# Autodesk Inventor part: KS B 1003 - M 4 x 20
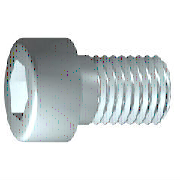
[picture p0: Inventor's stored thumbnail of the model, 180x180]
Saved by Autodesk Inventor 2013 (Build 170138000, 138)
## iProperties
IsCustomPart: 1
Company: 한국ATC센터
Created: 2009-02
Part Number: KS B 1003 - M 4 x 20
Material: 강철, 연강
Description: 6각머리 태핑 나사
Document SubType Name: Modeling
Standard: KS B 1003
Designer: KYOUNG IL JANG
Standards Organization: KS
Language: ko-KR
Size Designation: M 4 x 20
Categories: <MemberInstance><Categories><Category DisplayName="조임쇠" InternalName="e4da775c-781d-43d5-af7c-5136215cf5a6" Mnemonic="FSTN"><Category DisplayName="볼트" InternalN
Density: 7.86 g/cm^3
Mass: 2.43327 g
Surface Area: 3.56234 cm^2
Volume: 0.309576 cm^3
Vendor: CBT Solutions
Author: KYOUNG IL JANG
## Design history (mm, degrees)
sketch "스케치1"
  geometry: L1 (-1, 0)-(20, 0); L2 (20, 0)-(20, 2); L3 (20, 2)-(1.75, 2); L4 (1.75, 2)-(1.32, 2); L5 (1.32, 2)-(0, 2); L6 (0, 2)-(0, 3.5); L7 (0, 3.5)-(-4, 3.5); L8 (-4, 3.5)-(-4, 1.732); L9 (-4, 1.732)-(-2, 1.732); L10 (-2, 1.732)-(-1, 0); L11 (-8.8, 0)-(24.8, 0) reference; L12 (0, -0.7)-(0, 4.2) reference; L13 (1.75, 2)-(0, 2)
  constraints: 22 end point, 6 parallel, 2 collinear, 2 perpendicular, 1 horizontal, 1 point on line
  dimensions: "d1" = 18.25 distance from line of L3.end L2 (= GEL); "d2" = 0.42952 distance of L4.end L3.end (computed from GAL); "d3" = 4 distance between parallel lines of L8 L6 (= KOH); "d4" = 2 distance of L8.end L9.end (= INTI); "d5" = 60 deg angle of L10 L1; "d6" = 4 diameter of L3 L1 (= GD); "d7" = 4 diameter of L5 L1 (= BDM); "d8" = 3.4641 diameter of L9 L1 (= 1.1547 x SW); "d9" = 7 diameter of L7 L1 (= KOD); "d26" = 20 distance between parallel lines of L12 L2 (= NLG)
revolve "본체" sketch "스케치1" stored, may be unused: angle "d10" = 90 deg
sketch "스케치2"
  geometry: L1 (0, -4.9)-(0, 4.9) reference; L2 (-4.9, 0)-(4.9, 0) reference; L3 (1.732, 0)-(0.866, -1.5); L4 (0.866, -1.5)-(-0.866, -1.5); L5 (-0.866, -1.5)-(-1.732, 0); L6 (-1.732, 0)-(-0.866, 1.5); L7 (-0.866, 1.5)-(0.866, 1.5); L8 (0.866, 1.5)-(1.732, 0); 2 further points
  constraints: 12 end point, 1 coincident, 1 horizontal alignment, 1 point on line, 12 other
extrude "슬롯" join sketch "스케치2" stored distance "d11" = 10; taper "d12" = 0 deg
workplane "Work Plane1"
fillet "Fillet2" dims "d30" = 0.1 (= R)
sketch "스케치4"
  geometry: C1 r 2.574 at (0, 0); 1 further point
  constraints: 1 centre point, 1 coincident
extrude "돌출3" cut sketch "스케치4" distance "d31" = 2; taper "d32" = 0 deg
chamfer "모따기3" distance "d33" = 0.4; stored, may be unused: second distance "d34" = 2, angle "d35" = 45 deg
body "Solid1"
fillet "모깎기1" dims "d17" = 0.4 (= RR)
feature "스레드" dims "d13" = 18.25 (= GEL), "d14" = 0
chamfer "모따기1" distance "d15" = 0.42941 (= -0.5 x SPD + 0.5 x GD); stored, may be unused: second distance "d16" = 0.42941 (= GUL), angle "d27" = 45 deg
other parameters: "GD" = 4 (= NND) [user parameter; used in 2 equation terms], "NLG" = 20 [user parameter; used in 1 equation term], "GEL" = 18.25 [user parameter; used in 2 equation terms], "KOD" = 7 [user parameter; used in 1 equation term], "KOH" = 4 [user parameter; used in 1 equation term], "INTI" = 2 [user parameter; used in 1 equation term], "GAL" = 0.42941 (= 0.61345 x PTC) [user parameter; used in 1 equation term], "GUL" = 0.42941 (= 0.61345 x PTC) [user parameter; used in 1 equation term], "BDM" = 4 (= NND) [user parameter; used in 1 equation term], "SW" = 3 [user parameter; used in 2 equation terms], "RR" = 0.4 [user parameter; used in 1 equation term], "SPD" = 3.14117 (= NND - 1.2269 x PTC) [user parameter; used in 1 equation term], "d19" = 0, "d28" = 0, "d29" = 0, "R" = 0.1 [user parameter; used in 1 equation term], "PHH" = 0.2 [user parameter], "GD1" = 3.14117 (= THREADDIA - 1.2269 x PTC) [user parameter], "THREADDIA" = 4 [user parameter; used in 1 equation term], "FAWI" = 45 deg [user parameter], "TPU" = 14.28571 (computed from PTC) [user parameter], "PTC" = 0.7 [user parameter; used in 5 equation terms], "NND" = 4 [user parameter; used in 3 equation terms], "TOA" = 30 deg [user parameter], "E0" = 3.465 (= 1.155 x SW) [user parameter]
